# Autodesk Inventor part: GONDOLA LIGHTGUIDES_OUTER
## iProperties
Shininess: 64.0
Length Units: 11272
Angle Units: 11279
Time Units: 11290
Mass Units: 11286
Length Display Precision: 3
Angle Display Precision: 2
Compacted: True
Part Number: GONDOLA LIGHTGUIDES_OUTER
Document SubType Name: Modeling
Created: 2004-08
Designer: John Blackburn
Manufacturer: Standard
Standards Organization: Custom
Material: Lexan, Clear
Density: 0.0
Volumn: 0.0
Area: 0.0
PropertySet Name: Model Information
Control State: 0
Master: False
Checked Out: False
Author: John Blackburn
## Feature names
1. Base1
